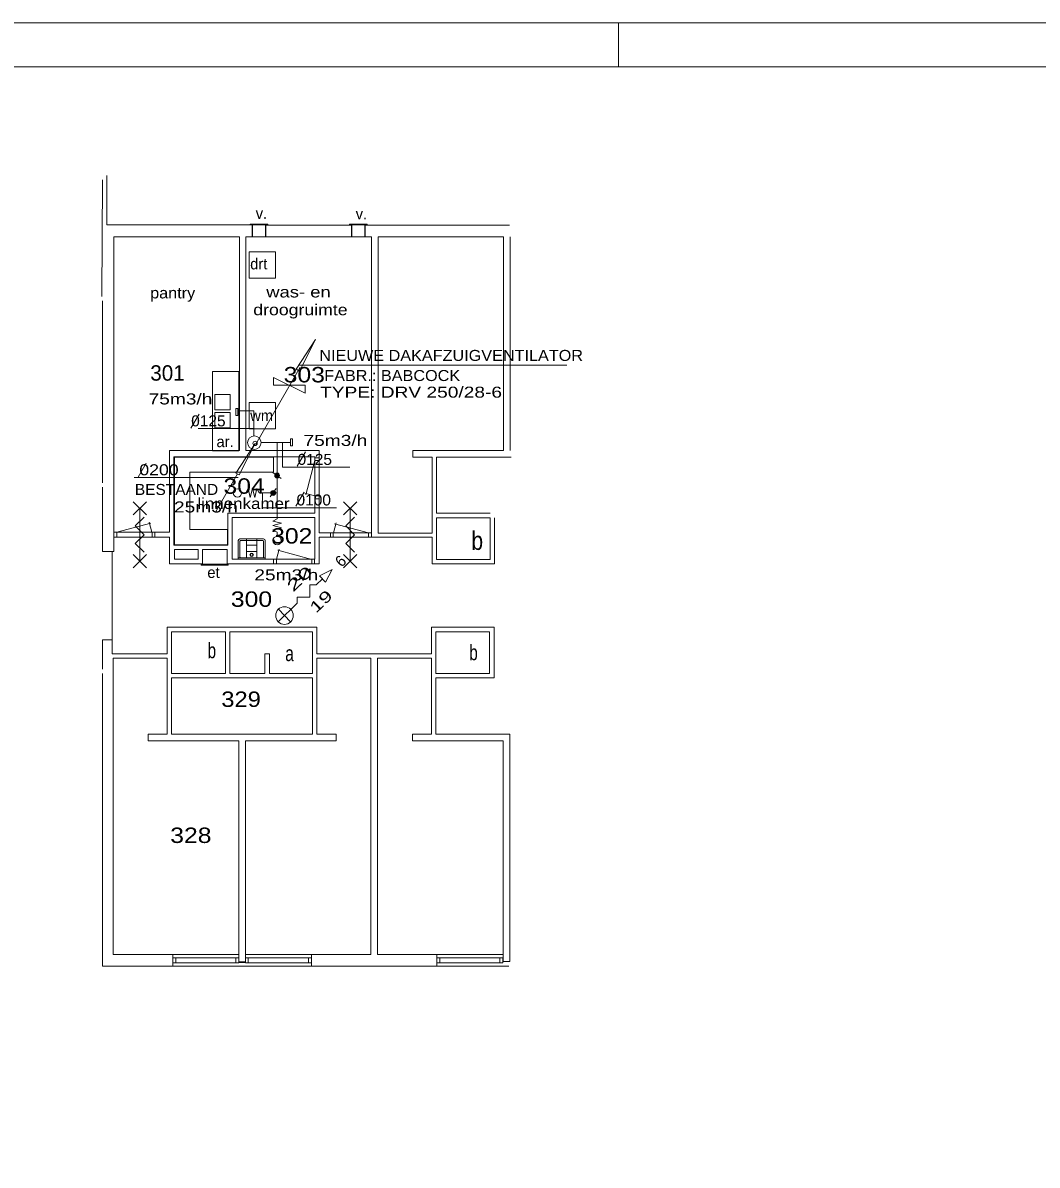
# Model space of a CAD drawing. Extents: x 295824 to 414724, y 24924 to 109024.
# Drawn here: x 359197 to 382224, y 83088 to 109024 of the extents above; entities that cross this region are included whole.
import ezdxf
from ezdxf.enums import TextEntityAlignment as Align

# ---------------------------------------------------------------- set-up
doc = ezdxf.new("R2010")
doc.units = 0
doc.header["$LTSCALE"] = 100
for name, color, linetype, lineweight in [('1', 7, 'Continuous', 13), ('24', 7, 'Continuous', 13), ('61', 7, 'Continuous', 13)]:
    doc.layers.add(name, color=color, linetype=linetype, lineweight=lineweight)

msp = doc.modelspace()

# ---------------------------------------------------------------- hatches: boundary and pattern name
at = {"layer": '24'}
for points in [[(364914.5, 98746.8, 1), (365023.1, 98746.8, 1)], [(364879.2, 98404.3, 1), (364879.2, 98295.7, 1)]]:
    msp.add_hatch(color=256, dxfattribs=at).paths.add_polyline_path(points)

# ---------------------------------------------------------------- linework, layer by layer
at = {"layer": '1'}
for p, q in [((372723.6, 108023.8), (372723.6, 109023.8)), ((364451.2, 99816.7), (363177, 99816.7)), ((363569.2, 97916), (364069.2, 98782))]:
    msp.add_line(p, q, dxfattribs=at)
for points in [[(414723.6, 109023.8), (304995.6, 109023.8), (295823.6, 109023.8)], [(304995.6, 25923.8), (413723.6, 25923.8), (413723.6, 108023.8), (304995.6, 108023.8)], [(364076.5, 100216.7), (364442.9, 100216.7), (364442.9, 99641.7)]]:
    msp.add_lwpolyline(points, dxfattribs=at)
msp.add_lwpolyline([(364469.2, 99475), (364105.2, 98761), (364033.2, 98803)], close=True, dxfattribs=at)
msp.add_circle((364469.2, 99474.7), 50, dxfattribs=at)
at = {"layer": '24'}
for p, q in [((364483.1, 99454.2), (365493.7, 101204.5)), ((365458.8, 101252.7), (371549.1, 101252.7)), ((363197, 100138.5), (363012.7, 99819.2)), ((364606, 99492.2), (365268.6, 99492.2)), ((364968.8, 97811.4), (364968.8, 99492.2)), ((365612.2, 99280.2), (365427.8, 98960.9)), ((361995.7, 99028.4), (361811.4, 98709.1)), ((365060.4, 98676), (364868.9, 98817.7)), ((361724.5, 98698.1), (364085.3, 98698.1)), ((364610.1, 98350), (364968.8, 98350)), ((364808.4, 98258.4), (364950.1, 98449.9)), ((365580.7, 98367.6), (365396.4, 98048.3))]:
    msp.add_line(p, q, dxfattribs=at)
for points in [[(365839.1, 101831.4), (365475.1, 101117.4), (365403.1, 101159.4)], [(365604.1, 100614.9), (365604.1, 100794.9), (364884.1, 100794.9), (364884.1, 100974.9)], [(364077.7, 100271.3), (364034.2, 100271.3), (364034.2, 100109), (364077.7, 100109)], [(365318.6, 99579.7), (365275.1, 99579.7), (365275.1, 99417.4), (365318.6, 99417.4)]]:
    msp.add_lwpolyline(points, close=True, dxfattribs=at)
for points in [[(365091.5, 99481.1), (365091.5, 98938.3), (366616.7, 98938.3)], [(364160.1, 98350), (364260.1, 98350), (364310.1, 98450), (364360.1, 98250), (364410.1, 98450), (364460.1, 98250), (364510.1, 98450), (364560.1, 98350), (364610.1, 98350)], [(364635.5, 98348.2), (364635.5, 98009.9), (366317.9, 98009.9)], [(364968.8, 97361.4), (364968.8, 97461.4), (364868.8, 97511.4), (365068.8, 97561.4), (364868.8, 97611.4), (365068.8, 97661.4), (364868.8, 97711.4), (364968.8, 97761.4), (364968.8, 97811.4)]]:
    msp.add_lwpolyline(points, dxfattribs=at)
for centre, radius in [((364452.5, 99492.2), 153.6), ((364968.8, 98746.8), 54.3), ((364068.4, 98350), 95), ((364879.2, 98350), 54.3), ((364968.8, 97269.8), 95)]:
    msp.add_circle(centre, radius, dxfattribs=at)
at = {"layer": '61'}
for p, q in [((361105, 105559.9), (361105, 104434.8)), ((360992, 102809.9), (361005, 105459.9)), ((361105, 104434.8), (364405.1, 104434.8)), ((364758.7, 104455), (364360.4, 104455)), ((364360.4, 104455), (364360.4, 104439.9)), ((364758.7, 104439.9), (364360.4, 104439.9)), ((364405.1, 104434.8), (364405.1, 104164.8)), ((364410.7, 104439.9), (364410.7, 104165.5)), ((364709.4, 104439.9), (364709.4, 104165.5)), ((364715.8, 104433.5), (364715.8, 104165)), ((364715.8, 104433.5), (366658.8, 104433.5)), ((364758.7, 104455), (364758.7, 104439.9)), ((367012.4, 104455), (366614.1, 104455)), ((366614.1, 104455), (366614.1, 104439.9)), ((367012.4, 104439.9), (366614.1, 104439.9)), ((366658.8, 104433.5), (366658.8, 104165)), ((366664.4, 104439.9), (366664.4, 104165.5)), ((366963.1, 104439.9), (366963.1, 104165.5)), ((366969.5, 104433.4), (370247.5, 104433.4)), ((366969.5, 104433.4), (366969.5, 104163.4)), ((367012.4, 104455), (367012.4, 104439.9)), ((361262, 97018.8), (361262, 104163.4)), ((364262, 104164.8), (364405.1, 104164.8)), ((364262, 99313.4), (364262, 104163.5)), ((367112, 104163.5), (364262, 104163.5)), ((364709.4, 104165.5), (364410.7, 104165.5)), ((364715.8, 104165), (364861.6, 104165)), ((366512.1, 104165), (366658.8, 104165)), ((366963.1, 104165.5), (366664.4, 104165.5)), ((366969.5, 104163.4), (367112, 104163.4)), ((367112, 97344.7), (367112, 104163.5)), ((370262, 104163.4), (370262, 99313.4)), ((361005, 102709.9), (361005, 98580.1)), ((363552.5, 100587.8), (363902.5, 100587.8)), ((363903.3, 100586.2), (363903.3, 100236.2)), ((363902.5, 100233.7), (363552.5, 100233.7)), ((363552.5, 100179.6), (363902.5, 100179.6)), ((363903.3, 100178), (363903.3, 99828)), ((363902.5, 99825.5), (363552.5, 99825.5)), ((362527.3, 99313.4), (362527.3, 97457.3)), ((362627.3, 97163.1), (362627.3, 99168.1)), ((364262, 99313.4), (365927.3, 99313.4)), ((365825.3, 99083.9), (365618.3, 98311.1)), ((365926.8, 99150.1), (365826, 99150.1)), ((365924.8, 99083.1), (365827.3, 99083.1)), ((365925.2, 99150.1), (365828.5, 99150.1)), ((368587, 97888.4), (368587, 99162.1)), ((370283.5, 99162.1), (368587, 99162.1)), ((365824.7, 98285.5), (365597.9, 98346.2)), ((362000.3, 98152), (361700.3, 97852)), ((361700.3, 98152), (362000.3, 97852)), ((365924.6, 98283.1), (365826, 98283.1)), ((365924.8, 98216.1), (365826, 98216.1)), ((366777.5, 98152), (366477.5, 97852)), ((366477.5, 98152), (366777.5, 97852)), ((361850.3, 96802), (361850.3, 98002)), ((366627.5, 96802), (366627.5, 98002)), ((368587, 97888.4), (369807, 97888.4)), ((369907, 96738.4), (369907, 97788.4)), ((361328.9, 97457.9), (362101.7, 97665)), ((362127.4, 97458.6), (362066.6, 97685.4)), ((366248, 97444.2), (366308.8, 97671.1)), ((367046.5, 97443.6), (366273.7, 97650.6)), ((361329.7, 97343.3), (361329.7, 97457.3)), ((362129.7, 97343.3), (362129.7, 97457.3)), ((362196.7, 97343.3), (362196.7, 97457.3)), ((362527.3, 96743.1), (362527.3, 97343.3)), ((364087.5, 97269.8), (364087.5, 96854.8)), ((364662.5, 97304.8), (364122.5, 97304.8)), ((364137.5, 97269.8), (364647.5, 97269.8)), ((364272.5, 96879.8), (364272.5, 97304.8)), ((364512.5, 96879.8), (364512.5, 97304.8)), ((364697.5, 96854.8), (364697.5, 97269.8)), ((365927.3, 97344.7), (367115.7, 97344.7)), ((365927.3, 97343.1), (365927.3, 96743.1)), ((366178.7, 97344.1), (366178.7, 97443)), ((366245.7, 97344.3), (366245.7, 97443)), ((367045.7, 97344.1), (367045.7, 97443)), ((367112, 97344.7), (368487, 97344.7)), ((367112.7, 97344.7), (367112.7, 97443.1)), ((368487, 96738.4), (368487, 97344.7)), ((361225, 97018.8), (361225, 94699.2)), ((363847.3, 97163.1), (362627.3, 97163.1)), ((362637.3, 96843.1), (362637.3, 97063.1)), ((363177.3, 97063.1), (362637.3, 97063.1)), ((363177.3, 96843.1), (363177.3, 97063.1)), ((363277.3, 96743.1), (363277.3, 97063.1)), ((363837.3, 97063.1), (363277.3, 97063.1)), ((363837.3, 96743.1), (363837.3, 97063.1)), ((364122.5, 96894.8), (364122.5, 97254.8)), ((364512.5, 97163.1), (364272.5, 97163.1)), ((364512.5, 97021.5), (364272.5, 97021.5)), ((364662.5, 97254.8), (364662.5, 96894.8)), ((364956.7, 96843.2), (365017.5, 97070.1)), ((365755.2, 96842.6), (364982.4, 97049.6)), ((362000.3, 96952), (361700.3, 96652)), ((361700.3, 96952), (362000.3, 96652)), ((363277.3, 96743.1), (362527.3, 96743.1)), ((363177.3, 96843.1), (362637.3, 96843.1)), ((365927.3, 96743.1), (363837.3, 96743.1)), ((364687.5, 96879.8), (364097.5, 96879.8)), ((364097.5, 96844.8), (364687.5, 96844.8)), ((364887.4, 96743.1), (364887.4, 96842)), ((364954.4, 96743.3), (364954.4, 96842)), ((365754.4, 96743.1), (365754.4, 96842)), ((365821.4, 96743.1), (365821.4, 96842)), ((366777.5, 96952), (366477.5, 96652)), ((366477.5, 96952), (366777.5, 96652)), ((363243.1, 96736), (363861.5, 96736)), ((363243.1, 96708.2), (363243.1, 96736)), ((369907, 96738.4), (368487, 96738.4)), ((364998.1, 95710.2), (365276, 95422.5)), ((362474.3, 95299.2), (362474.3, 94699.2)), ((365874.3, 95299.2), (362474.3, 95299.2)), ((365874.3, 94699.2), (365874.3, 95299.2)), ((369894.3, 95299.2), (369894.3, 94149.2)), ((362474.3, 94699.2), (361225, 94699.2)), ((361005, 94250.3), (361005, 87604.2)), ((368574.3, 94149.2), (368574.3, 92874.6)), ((368574.3, 94149.2), (369894.3, 94149.2)), ((370249.3, 92874.6), (368574.3, 92874.6)), ((370249.3, 87713.6), (370249.3, 92874.6)), ((361249.3, 87874.2), (364099.3, 87874.2)), ((362600.6, 87599.6), (362600.6, 87869.6)), ((362667.3, 87677.8), (362667.3, 87791.7)), ((364032.3, 87677.2), (364032.3, 87791.2)), ((364099.3, 87707.2), (364249.3, 87707.2)), ((364099.3, 87692.2), (364249.3, 87692.2)), ((367099.3, 87874.2), (364249.3, 87874.2)), ((364315.8, 87678.2), (364315.8, 87792.2)), ((365680.2, 87677.9), (365680.2, 87791.5)), ((365748.6, 87599.6), (365748.6, 87869.7)), ((367249.3, 87874.2), (370099.3, 87874.2)), ((368597.5, 87602.1), (368597.5, 87872.1)), ((368664.2, 87677.8), (368664.2, 87791.7)), ((370029.2, 87677.2), (370029.2, 87791.2)), ((370097.8, 87713.6), (370249.3, 87713.6)), ((361005, 87604.2), (370229.2, 87604.2))]:
    msp.add_line(p, q, dxfattribs=at)
for points in [[(361262, 104163.4), (364112, 104163.4), (364112, 99313.4), (362527.3, 99313.4)], [(363504.2, 99307.9), (364098.9, 99307.9), (364098.9, 101107.9)], [(363504.2, 99307.9), (363504.2, 101107.9), (364098.9, 101107.9)], [(363553.3, 100236.2), (363553.3, 100586.2), (363552.5, 100587.8)], [(363553.3, 99828), (363553.3, 100178), (363552.5, 100179.6)], [(362627.3, 99168.1), (365827.3, 99168.1), (365827.3, 97893.1), (363847.3, 97893.1), (363847.3, 97163.1)], [(365927.3, 99313.4), (365927.3, 97443.1), (367112.7, 97443.1)], [(361005, 98480.1), (361005, 97018.8), (361262, 97018.8)], [(361950.3, 97002), (361750.3, 97202), (361950.3, 97402), (361750.3, 97602), (361950.3, 97802)], [(366727.5, 97002), (366527.5, 97202), (366727.5, 97402), (366527.5, 97602), (366727.5, 97802)], [(361262.7, 97343.3), (361262.7, 97457.3), (362527.3, 97457.3)], [(362527.3, 97343.3), (361262.7, 97343.3), (361262.7, 97457.3)], [(363243.1, 96708.2), (363861.5, 96708.2), (363861.5, 96736)], [(364993.2, 95427.4), (365424.8, 95844.2), (365427.3, 95985.6), (365710.1, 95980.7), (365715, 96263.5), (365856.4, 96261), (366000.2, 96399.9)], [(369894.3, 95299.2), (368474.3, 95299.2), (368474.3, 94699.2)], [(361225, 95018.8), (361005, 95018.8), (361005, 94350.3)], [(365874.3, 94699.2), (368474.3, 94699.2), (367249.3, 94699.2)], [(364099.3, 87692.2), (364099.3, 92724.2), (362039.3, 92724.2), (362039.3, 92874.2), (362474.3, 92874.2), (362474.3, 94599.2), (361249.3, 94599.2), (361249.3, 87874.2)], [(364249.3, 87692.2), (364249.3, 92724.2), (366309.3, 92724.2), (366309.3, 92874.2), (365874.3, 92874.2), (365874.3, 94599.2), (367099.3, 94599.2), (367099.3, 87874.2)], [(370099.3, 87713.6), (370099.3, 92724.2), (368039.3, 92724.2), (368039.3, 92874.2), (368474.3, 92874.2), (368474.3, 94599.2), (367249.3, 94599.2), (367249.3, 87874.2)]]:
    msp.add_lwpolyline(points, dxfattribs=at)
for points in [[(367262, 104163.4), (370112, 104163.4), (370112, 99313.4), (368052, 99313.4), (368052, 99163.4), (368487, 99163.4), (368487, 97438.4), (367262, 97438.4)], [(364333.5, 103228.2), (364333.5, 103828.2), (364933.5, 103828.2), (364933.5, 103228.2)], [(364333.5, 99805.5), (364333.5, 100405.5), (364933.5, 100405.5), (364933.5, 99805.5)], [(362640, 97169.8), (362640, 99163.4), (364890.7, 99163.4), (364890.7, 98823.2), (362990, 98823.2), (362990, 97520.9), (363840.2, 97520.9), (363840.2, 97169.8)], [(363947.3, 97793.1), (365827.3, 97793.1), (365827.3, 96843.1), (363947.3, 96843.1)], [(368587, 97788.4), (369807, 97788.4), (369807, 96838.4), (368587, 96838.4)], [(366069.7, 96328), (365930.8, 96471.9), (366216, 96608.3)], [(362574.3, 94249.2), (363794.3, 94249.2), (363794.3, 95199.2), (362574.3, 95199.2)], [(363894.3, 94249.2), (364694.3, 94249.2), (364694.3, 94699.2), (364794.3, 94699.2), (364794.3, 94249.2), (365774.3, 94249.2), (365774.3, 95199.2), (363894.3, 95199.2)], [(368574.3, 94249.2), (369794.3, 94249.2), (369794.3, 95199.2), (368574.3, 95199.2)], [(362574.3, 92874.2), (365774.3, 92874.2), (365774.3, 94149.2), (362574.3, 94149.2)], [(362600.5, 87677.7), (362600.5, 87791.7), (364099.2, 87791.7), (364099.2, 87677.7)], [(364249.5, 87677.9), (364249.5, 87791.9), (365748.9, 87791.9), (365748.9, 87677.9)], [(368597.4, 87677.7), (368597.4, 87791.7), (370096, 87791.7), (370096, 87677.7)]]:
    msp.add_lwpolyline(points, close=True, dxfattribs=at)
for centre, radius in [((364392.5, 96944.8), 40), ((364392.5, 96944.8), 30), ((365137, 95566.3), 200)]:
    msp.add_circle(centre, radius, dxfattribs=at)
for centre, radius, start, end in [((364122.5, 97269.8), 35, 90, 180), ((364137.5, 97254.8), 15, 90, 180), ((364647.5, 97254.8), 15, 0, 90), ((364662.5, 97269.8), 35, 0, 90), ((364097.5, 96869.8), 10, 90, 180), ((364097.5, 96854.8), 10, 180, 270), ((364137.5, 96894.8), 15, 180, 270), ((364647.5, 96894.8), 15, 270, 0), ((364687.5, 96869.8), 10, 0, 90), ((364687.5, 96854.8), 10, 270, 0)]:
    msp.add_arc(centre, radius, start, end, dxfattribs=at)

# ---------------------------------------------------------------- texts
at = {"layer": '24'}
for s, width, p in [('NIEUWE DAKAFZUIGVENTILATOR', 1.1, (365927.4, 101347.4)), ('FABR.: BABCOCK', 1.1, (366039.3, 100891.1)), ('TYPE: DRV 250/28-6', 1.3, (365945, 100513.4)), ('75m3/h', 1.3, (362051.1, 100359.6)), ('0125', 1.05, (363018.8, 99862.2)), ('75m3/h', 1.3, (365568.6, 99417.1)), ('0125', 1.05, (365434, 98987.2)), ('0200', 1.2, (361841.1, 98751.2)), ('BESTAAND', 1.05, (361739.9, 98304.3)), ('0100', 1.05, (365410.4, 98066.7)), ('25m3/h', 1.3, (362628.3, 97906.6)), ('25m3/h', 1.3, (364452.3, 96364.6))]:
    msp.add_text(s, height=250, dxfattribs=dict(at, width=width)).set_placement(p)
at = {"layer": '61'}
for s, height, p in [('v.', 250, (364483.7, 104573.4)), ('v.', 250, (366752.9, 104563.3)), ('drt', 250, (364358, 103426.2)), ('301', 350, (362090.2, 100899.9)), ('wm', 250, (364358, 99983.8)), ('ar.', 250, (363592.7, 99390.2)), ('et', 250, (363385.6, 96421.1))]:
    msp.add_text(s, height=height, dxfattribs=at).set_placement(p)
for s, height, width, p in [('pantry', 250, 1.1, (362087.6, 102767.2)), ('was- en', 250, 1.25, (364723.1, 102788.8)), ('droogruimte', 250, 1.2, (364428.2, 102385.5)), ('303', 350, 1.2, (365118.2, 100860.5)), ('304', 350, 1.2, (363751.6, 98332)), ('linnenkamer', 250, 1.15, (363159.1, 97985.7)), ('302', 350, 1.2, (364833.1, 97200.7)), ('300', 350, 1.2, (363918.8, 95764.4)), ('329', 350, 1.15, (363702.5, 93491.8)), ('328', 350, 1.2, (362542.4, 90402.7))]:
    msp.add_text(s, height=height, dxfattribs=dict(at, width=width)).set_placement(p)
for s, height, width, p in [('b', 420, 0.85, (369513.2, 97056.4)), ('b', 350, 0.75, (363486.5, 94597.4)), ('a', 350, 0.75, (365251.3, 94531.5)), ('b', 350, 0.75, (369428.1, 94551.9))]:
    msp.add_text(s, height=height, dxfattribs=dict(at, width=width)).set_placement(p, align=Align.CENTER)
msp.add_text('6', height=250, rotation=44, dxfattribs=at).set_placement((366431.3, 96650.4))
for s, width, p in [('20', 1.75, (365331.4, 96085.6)), ('19', 1.5, (365851.5, 95604.1))]:
    msp.add_text(s, height=250, rotation=44, dxfattribs=dict(at, width=width)).set_placement(p)

doc.saveas('drawing.dxf')
